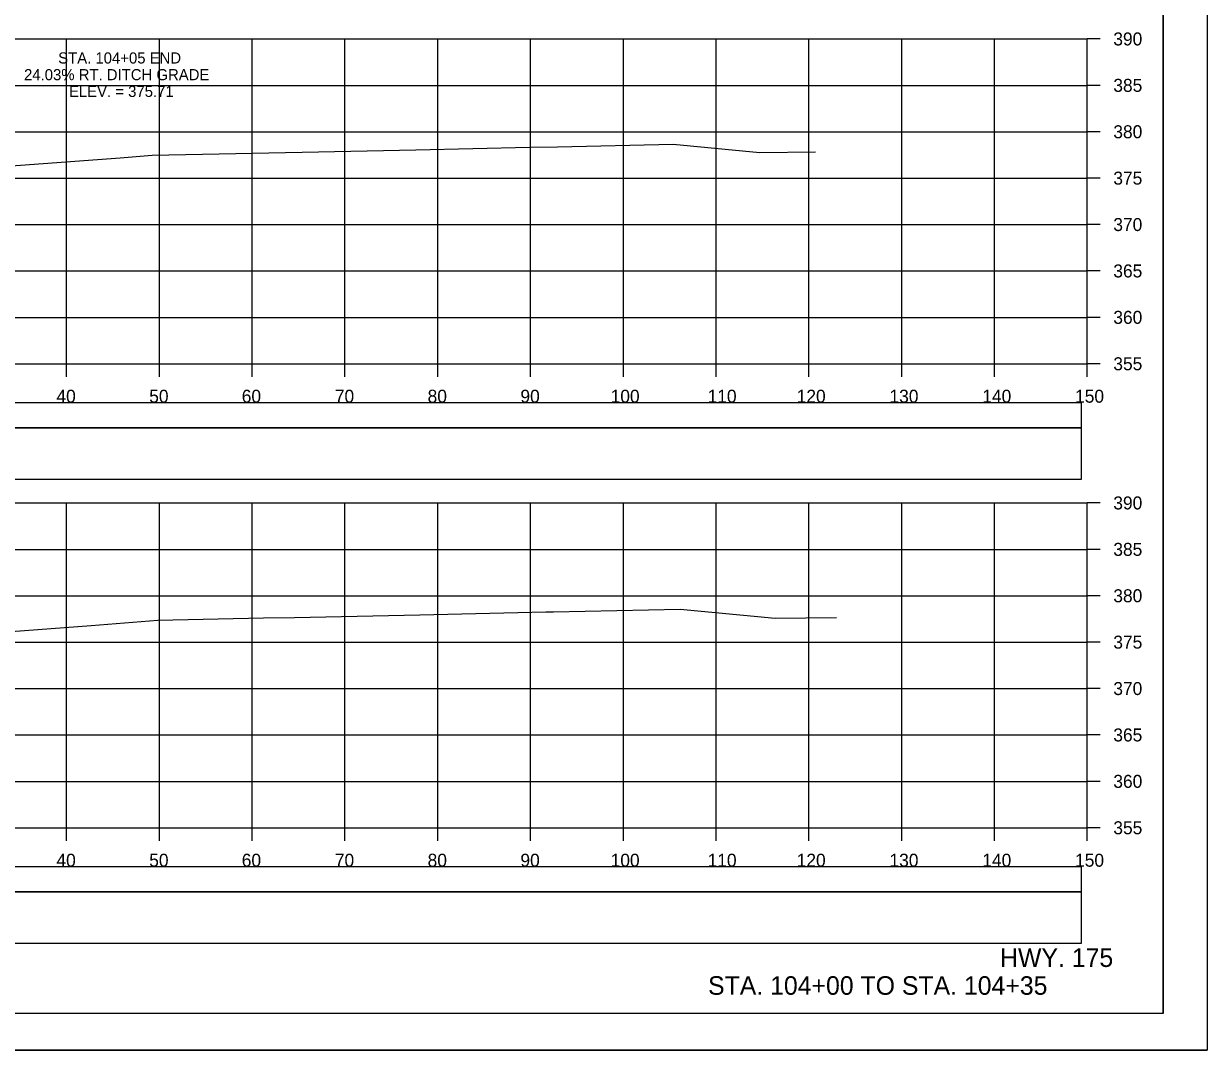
# Model space of a CAD drawing. Extents: x -37291014 to -37290680, y -936053 to -933067.
# Drawn here: x -37290807.7 to -37290680.2, y -935200 to -935089.3 of the extents above; entities that cross this region are included whole.
import ezdxf

# ---------------------------------------------------------------- set-up
doc = ezdxf.new("R2010")
doc.units = 0
for name, color, linetype in [('Default', 7, 'Continuous'), ('R_Axis', 7, 'Continuous'), ('R_Axis Annot', 7, 'Continuous'), ('R_Border', 7, 'Continuous'), ('R_Draft', 7, 'Continuous'), ('R_Exist Surface', 7, 'Continuous'), ('R_Grid', 7, 'Continuous'), ('R_No Plot', 7, 'Continuous'), ('R_Xsect Elev', 7, 'Continuous')]:
    doc.layers.add(name, color=color, linetype=linetype)

msp = doc.modelspace()

# ---------------------------------------------------------------- linework, layer by layer
at = {"layer": 'Default'}
for points in [[(-37290992.48, -935132.88), (-37290693.72, -935132.88), (-37290693.72, -935130.17), (-37290992.48, -935130.17)], [(-37290992.48, -935138.4), (-37290693.72, -935138.4), (-37290693.72, -935132.88), (-37290992.48, -935132.88)], [(-37290992.48, -935182.88), (-37290693.72, -935182.88), (-37290693.72, -935180.17), (-37290992.48, -935180.17)], [(-37290992.48, -935188.4), (-37290693.72, -935188.4), (-37290693.72, -935182.88), (-37290992.48, -935182.88)]]:
    msp.add_lwpolyline(points, close=True, dxfattribs=at)
at = {"layer": 'R_Axis'}
for p, q in [((-37290693.1, -935125.97), (-37290693.1, -935090.97)), ((-37290691.7, -935090.97), (-37290693.1, -935090.97)), ((-37290691.7, -935095.97), (-37290693.1, -935095.97)), ((-37290691.7, -935100.97), (-37290693.1, -935100.97)), ((-37290691.7, -935105.97), (-37290693.1, -935105.97)), ((-37290691.7, -935110.97), (-37290693.1, -935110.97)), ((-37290691.7, -935115.97), (-37290693.1, -935115.97)), ((-37290691.7, -935120.97), (-37290693.1, -935120.97)), ((-37290993.1, -935125.97), (-37290693.1, -935125.97)), ((-37290803.1, -935127.37), (-37290803.1, -935125.97)), ((-37290793.1, -935127.37), (-37290793.1, -935125.97)), ((-37290783.1, -935127.37), (-37290783.1, -935125.97)), ((-37290773.1, -935127.37), (-37290773.1, -935125.97)), ((-37290763.1, -935127.37), (-37290763.1, -935125.97)), ((-37290753.1, -935127.37), (-37290753.1, -935125.97)), ((-37290743.1, -935127.37), (-37290743.1, -935125.97)), ((-37290733.1, -935127.37), (-37290733.1, -935125.97)), ((-37290723.1, -935127.37), (-37290723.1, -935125.97)), ((-37290713.1, -935127.37), (-37290713.1, -935125.97)), ((-37290703.1, -935127.37), (-37290703.1, -935125.97)), ((-37290693.1, -935127.37), (-37290693.1, -935125.97)), ((-37290691.7, -935125.97), (-37290693.1, -935125.97)), ((-37290693.1, -935175.97), (-37290693.1, -935140.97)), ((-37290691.7, -935140.97), (-37290693.1, -935140.97)), ((-37290691.7, -935145.97), (-37290693.1, -935145.97)), ((-37290691.7, -935150.97), (-37290693.1, -935150.97)), ((-37290691.7, -935155.97), (-37290693.1, -935155.97)), ((-37290691.7, -935160.97), (-37290693.1, -935160.97)), ((-37290691.7, -935165.97), (-37290693.1, -935165.97)), ((-37290691.7, -935170.97), (-37290693.1, -935170.97)), ((-37290993.1, -935175.97), (-37290693.1, -935175.97)), ((-37290803.1, -935177.37), (-37290803.1, -935175.97)), ((-37290793.1, -935177.37), (-37290793.1, -935175.97)), ((-37290783.1, -935177.37), (-37290783.1, -935175.97)), ((-37290773.1, -935177.37), (-37290773.1, -935175.97)), ((-37290763.1, -935177.37), (-37290763.1, -935175.97)), ((-37290753.1, -935177.37), (-37290753.1, -935175.97)), ((-37290743.1, -935177.37), (-37290743.1, -935175.97)), ((-37290733.1, -935177.37), (-37290733.1, -935175.97)), ((-37290723.1, -935177.37), (-37290723.1, -935175.97)), ((-37290713.1, -935177.37), (-37290713.1, -935175.97)), ((-37290703.1, -935177.37), (-37290703.1, -935175.97)), ((-37290693.1, -935177.37), (-37290693.1, -935175.97)), ((-37290691.7, -935175.97), (-37290693.1, -935175.97))]:
    msp.add_line(p, q, dxfattribs=at)
at = {"layer": 'R_Border'}
for q in [(-37290684.92, -934990.51), (-37291001.1, -935195.97)]:
    msp.add_line((-37290684.92, -935195.97), q, dxfattribs=at)
at = {"layer": 'R_Exist Surface'}
for points in [[(-37290816.39, -935105.18), (-37290797.33, -935103.77), (-37290793.88, -935103.49), (-37290788.45, -935103.38), (-37290777.71, -935103.18), (-37290765.47, -935102.91), (-37290753.19, -935102.65), (-37290750.18, -935102.59), (-37290737.74, -935102.32), (-37290728.4, -935103.22), (-37290722.39, -935103.15)], [(-37290813.4, -935155.14), (-37290800.43, -935154.19), (-37290793.27, -935153.61), (-37290781.89, -935153.36), (-37290778.54, -935153.3), (-37290765.03, -935153.01), (-37290751.45, -935152.72), (-37290750.63, -935152.7), (-37290736.99, -935152.41), (-37290726.73, -935153.4), (-37290720.12, -935153.32)]]:
    msp.add_lwpolyline(points, dxfattribs=at)
at = {"layer": 'R_Grid'}
for p, q in [((-37290993.1, -935090.97), (-37290693.1, -935090.97)), ((-37290803.1, -935125.97), (-37290803.1, -935090.97)), ((-37290793.1, -935125.97), (-37290793.1, -935090.97)), ((-37290783.1, -935125.97), (-37290783.1, -935090.97)), ((-37290773.1, -935125.97), (-37290773.1, -935090.97)), ((-37290763.1, -935125.97), (-37290763.1, -935090.97)), ((-37290753.1, -935125.97), (-37290753.1, -935090.97)), ((-37290743.1, -935125.97), (-37290743.1, -935090.97)), ((-37290733.1, -935125.97), (-37290733.1, -935090.97)), ((-37290723.1, -935125.97), (-37290723.1, -935090.97)), ((-37290713.1, -935125.97), (-37290713.1, -935090.97)), ((-37290703.1, -935125.97), (-37290703.1, -935090.97)), ((-37290693.1, -935125.97), (-37290693.1, -935090.97)), ((-37290993.1, -935095.97), (-37290693.1, -935095.97)), ((-37290993.1, -935100.97), (-37290693.1, -935100.97)), ((-37290993.1, -935105.97), (-37290693.1, -935105.97)), ((-37290993.1, -935110.97), (-37290693.1, -935110.97)), ((-37290993.1, -935115.97), (-37290693.1, -935115.97)), ((-37290993.1, -935120.97), (-37290693.1, -935120.97)), ((-37290993.1, -935125.97), (-37290693.1, -935125.97)), ((-37290993.1, -935140.97), (-37290693.1, -935140.97)), ((-37290803.1, -935175.97), (-37290803.1, -935140.97)), ((-37290793.1, -935175.97), (-37290793.1, -935140.97)), ((-37290783.1, -935175.97), (-37290783.1, -935140.97)), ((-37290773.1, -935175.97), (-37290773.1, -935140.97)), ((-37290763.1, -935175.97), (-37290763.1, -935140.97)), ((-37290753.1, -935175.97), (-37290753.1, -935140.97)), ((-37290743.1, -935175.97), (-37290743.1, -935140.97)), ((-37290733.1, -935175.97), (-37290733.1, -935140.97)), ((-37290723.1, -935175.97), (-37290723.1, -935140.97)), ((-37290713.1, -935175.97), (-37290713.1, -935140.97)), ((-37290703.1, -935175.97), (-37290703.1, -935140.97)), ((-37290693.1, -935175.97), (-37290693.1, -935140.97)), ((-37290993.1, -935145.97), (-37290693.1, -935145.97)), ((-37290993.1, -935150.97), (-37290693.1, -935150.97)), ((-37290993.1, -935155.97), (-37290693.1, -935155.97)), ((-37290993.1, -935160.97), (-37290693.1, -935160.97)), ((-37290993.1, -935165.97), (-37290693.1, -935165.97)), ((-37290993.1, -935170.97), (-37290693.1, -935170.97)), ((-37290993.1, -935175.97), (-37290693.1, -935175.97))]:
    msp.add_line(p, q, dxfattribs=at)
at = {"layer": 'R_No Plot'}
msp.add_line((-37291013.5, -935199.95), (-37290680.17, -935199.95), dxfattribs=at)
for points in [[(-37291013.51, -934986.62), (-37290680.17, -934986.62), (-37290680.17, -935199.95), (-37291013.51, -935199.95)], [(-37290767.18, -934990.51), (-37290747.56, -934990.51), (-37290747.56, -935000.39), (-37290731.45, -935000.39), (-37290708.25, -935000.39), (-37290708.25, -935024.72), (-37290684.92, -935024.72), (-37290684.92, -935195.97), (-37291001.1, -935195.97), (-37291001.1, -934990.51)]]:
    msp.add_lwpolyline(points, close=True, dxfattribs=at)

# ---------------------------------------------------------------- texts
at = {"layer": 'R_Axis Annot'}
for s, p in [('390', (-37290690.3, -935091.67)), ('385', (-37290690.3, -935096.67)), ('380', (-37290690.3, -935101.67)), ('375', (-37290690.3, -935106.67)), ('370', (-37290690.3, -935111.67)), ('365', (-37290690.3, -935116.67)), ('360', (-37290690.3, -935121.67)), ('355', (-37290690.3, -935126.67)), ('40', (-37290804.19, -935130.17)), ('50', (-37290794.19, -935130.17)), ('60', (-37290784.22, -935130.17)), ('70', (-37290774.19, -935130.17)), ('80', (-37290764.19, -935130.17)), ('90', (-37290754.19, -935130.17)), ('100', (-37290744.47, -935130.17)), ('110', (-37290734.02, -935130.17)), ('120', (-37290724.42, -935130.17)), ('130', (-37290714.42, -935130.17)), ('140', (-37290704.42, -935130.17)), ('150', (-37290694.42, -935130.17)), ('390', (-37290690.3, -935141.67)), ('385', (-37290690.3, -935146.67)), ('380', (-37290690.3, -935151.67)), ('375', (-37290690.3, -935156.67)), ('370', (-37290690.3, -935161.67)), ('365', (-37290690.3, -935166.67)), ('360', (-37290690.3, -935171.67)), ('355', (-37290690.3, -935176.67)), ('40', (-37290804.19, -935180.17)), ('50', (-37290794.19, -935180.17)), ('60', (-37290784.22, -935180.17)), ('70', (-37290774.19, -935180.17)), ('80', (-37290764.19, -935180.17)), ('90', (-37290754.19, -935180.17)), ('100', (-37290744.47, -935180.17)), ('110', (-37290734.02, -935180.17)), ('120', (-37290724.42, -935180.17)), ('130', (-37290714.42, -935180.17)), ('140', (-37290704.42, -935180.17)), ('150', (-37290694.42, -935180.17))]:
    msp.add_text(s, height=1.4, dxfattribs=at).set_placement(p)
at = {"layer": 'R_Draft'}
for s, p in [('HWY. 175', (-37290702.5, -935190.97)), ('STA. 104+00 TO STA. 104+35', (-37290733.97, -935193.97))]:
    msp.add_text(s, height=2, dxfattribs=at).set_placement(p)
at = {"layer": 'R_Xsect Elev'}
for s, p in [('STA. 104+05 END ', (-37290804, -935093.62)), ('24.03% RT. DITCH GRADE', (-37290807.68, -935095.42)), ('ELEV. = 375.71', (-37290802.84, -935097.22))]:
    msp.add_text(s, height=1.2, dxfattribs=at).set_placement(p)

doc.saveas('drawing.dxf')
